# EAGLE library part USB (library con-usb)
USB Connectors
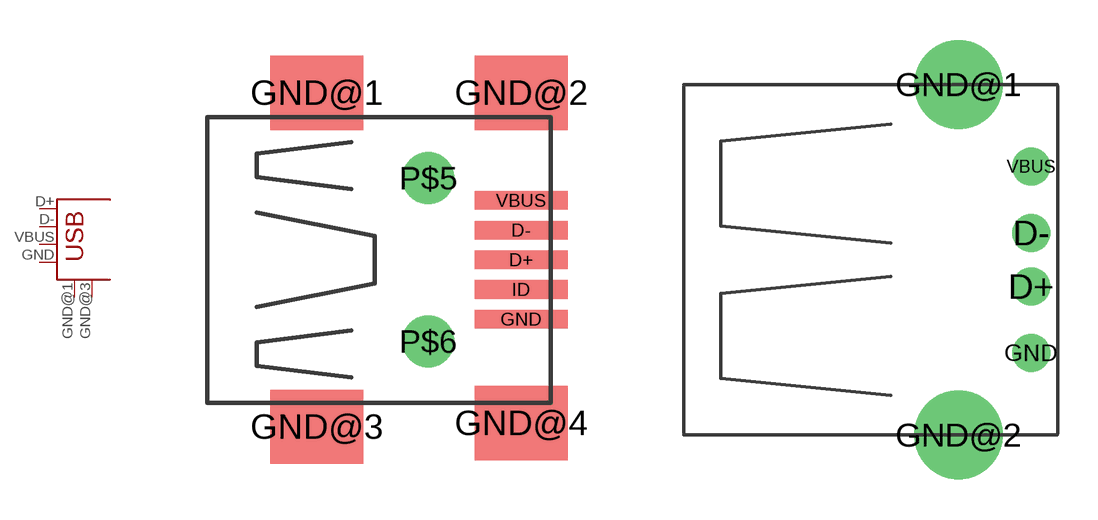
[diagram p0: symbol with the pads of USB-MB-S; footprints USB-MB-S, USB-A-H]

Designator prefix USB

## USB-MB-S  [USB-MB-S]
D+  D+
D-  D-
GND  GND
GND@1  GND
GND@3  GND
VBUS  VBUS

## USB-A-H  [USB-A-H]
D+  D+
D-  D-
GND  GND
GND@1  GND
GND@2  GND
VBUS  VBUS

## USB-B-H  [USB-B-H]
Pads as for USB-A-H

## USB-A-S  [USB-A-S]
Pads as for USB-A-H

## USB-MB-H  [USB-MB-H]
Pads as for USB-A-H

## USB-A-HU  [USB-A-HU]
Pads as for USB-MB-S

## Footprint USB-MB-S (pad centres in mm)
USB Series Mini-B Surface Mounted
smd 2.5 x 0.5: D+ 2.5,0; D- 2.5,0.8; GND 2.5,-1.6; ID 2.5,-0.8; VBUS 2.5,1.6
smd 2.5 x 2: GND@1 -3,4.5; GND@2 2.5,4.5; GND@3 -3,-4.5; GND@4 2.5,-4.4
drill 0.9 round: P$5 0,2.2; P$6 0,-2.2

## Footprint USB-A-H (pad centres in mm)
USB Series A Hole Mounted
drill 0.914 round: D+ 2.718,-1.003; D- 2.718,1.003; GND 2.718,-3.493; VBUS 2.718,3.493
drill 2.311 round: GND@1 0,6.566; GND@2 0,-6.566

## Footprint USB-B-H (pad centres in mm)
USB Series B Hole Mounted
drill 0.914 round: D+ 0,1.25; D- 1.981,1.25; GND 0,-1.25; VBUS 1.981,-1.25
drill 2.286 round: GND@1 -2.718,6.02; GND@2 -2.718,-6.02

## Footprint USB-A-S (pad centres in mm)
USB Series A Surface Mounted
smd 3 x 0.9: D+ 3.45,-1; D- 3.45,1; GND 3.45,-3; VBUS 3.45,3
drill 2.311 round: GND@1 0,6.566; GND@2 0,-6.566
